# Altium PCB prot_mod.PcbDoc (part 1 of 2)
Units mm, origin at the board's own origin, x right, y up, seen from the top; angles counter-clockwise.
Board outline 113 x 90 mm, 2 copper layers (Top Layer, Bottom Layer), stack 1.562 mm thick; 112 components, 43 nets, 249 pads, 37 vias.
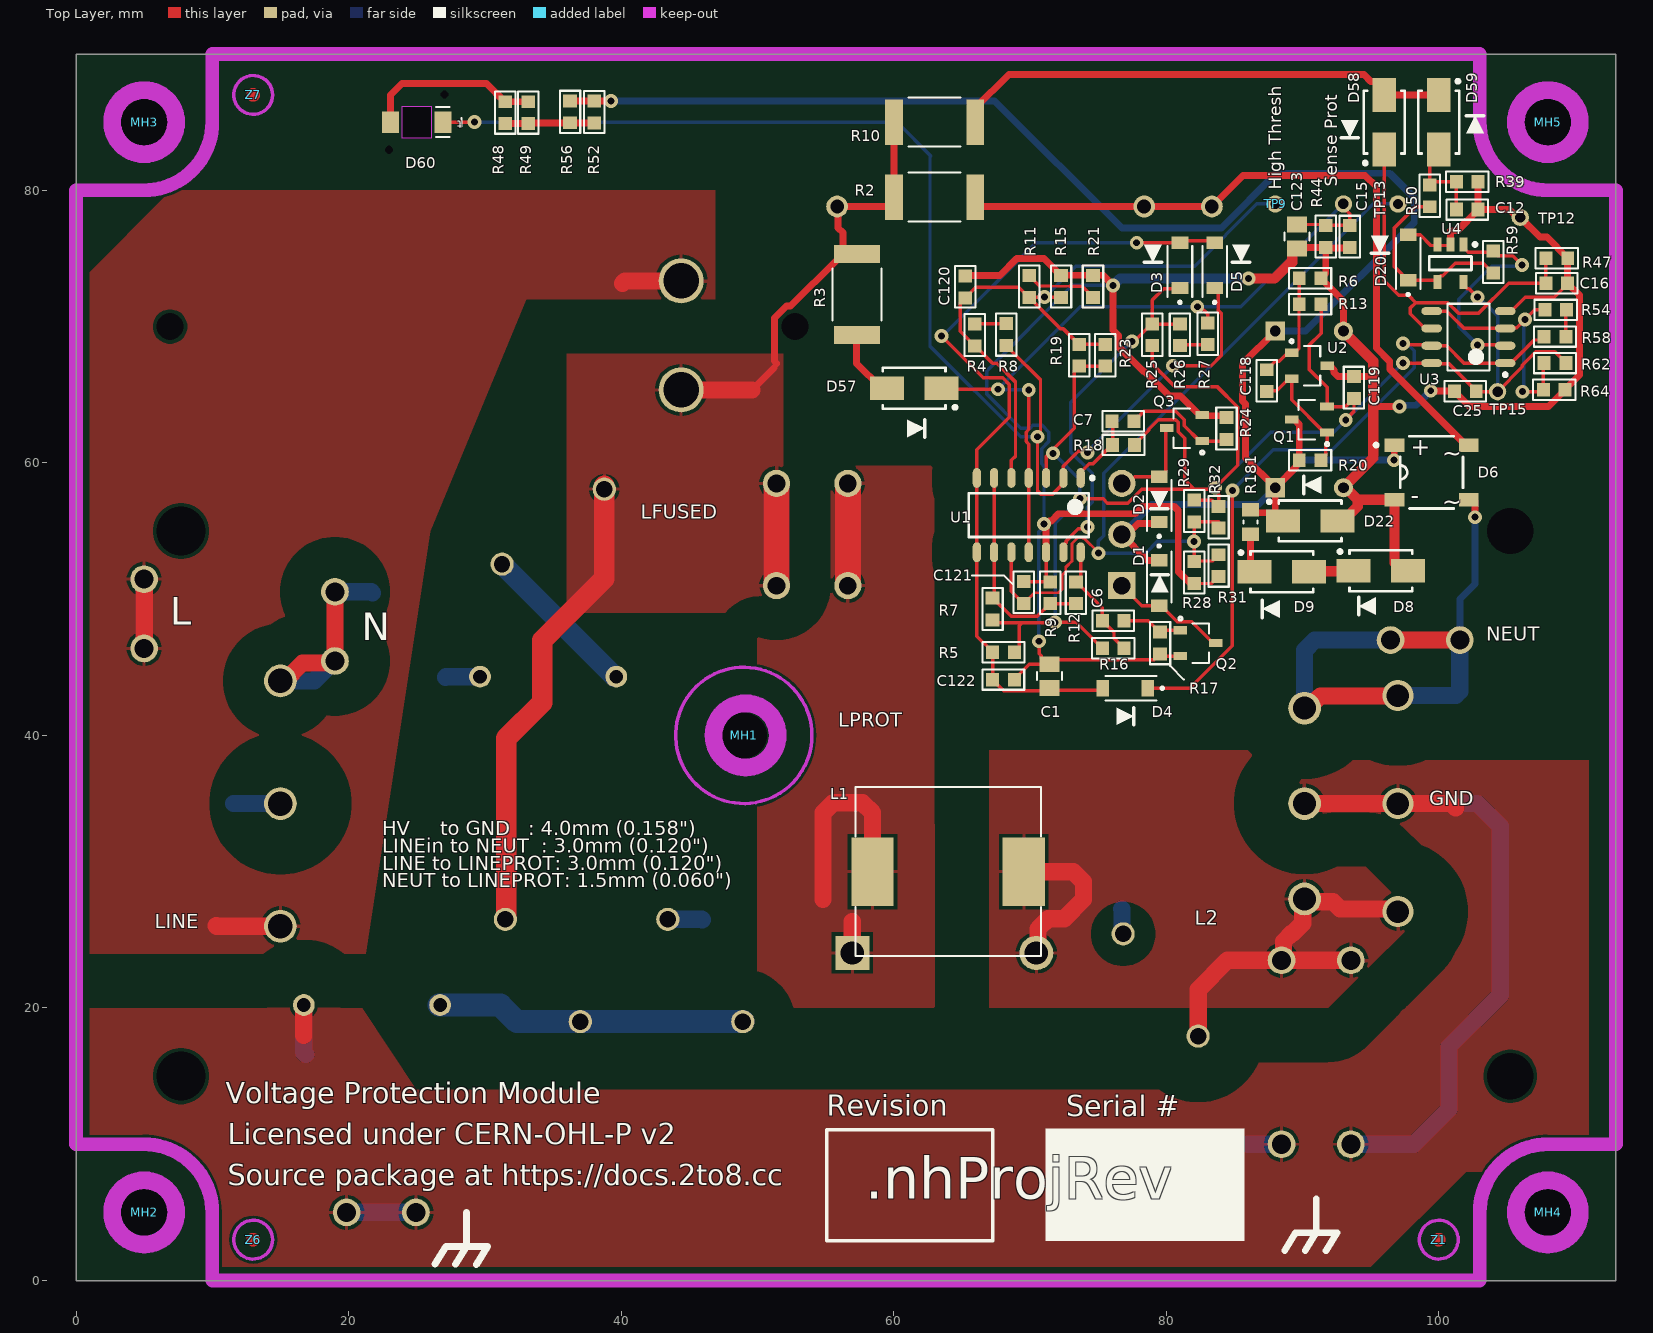
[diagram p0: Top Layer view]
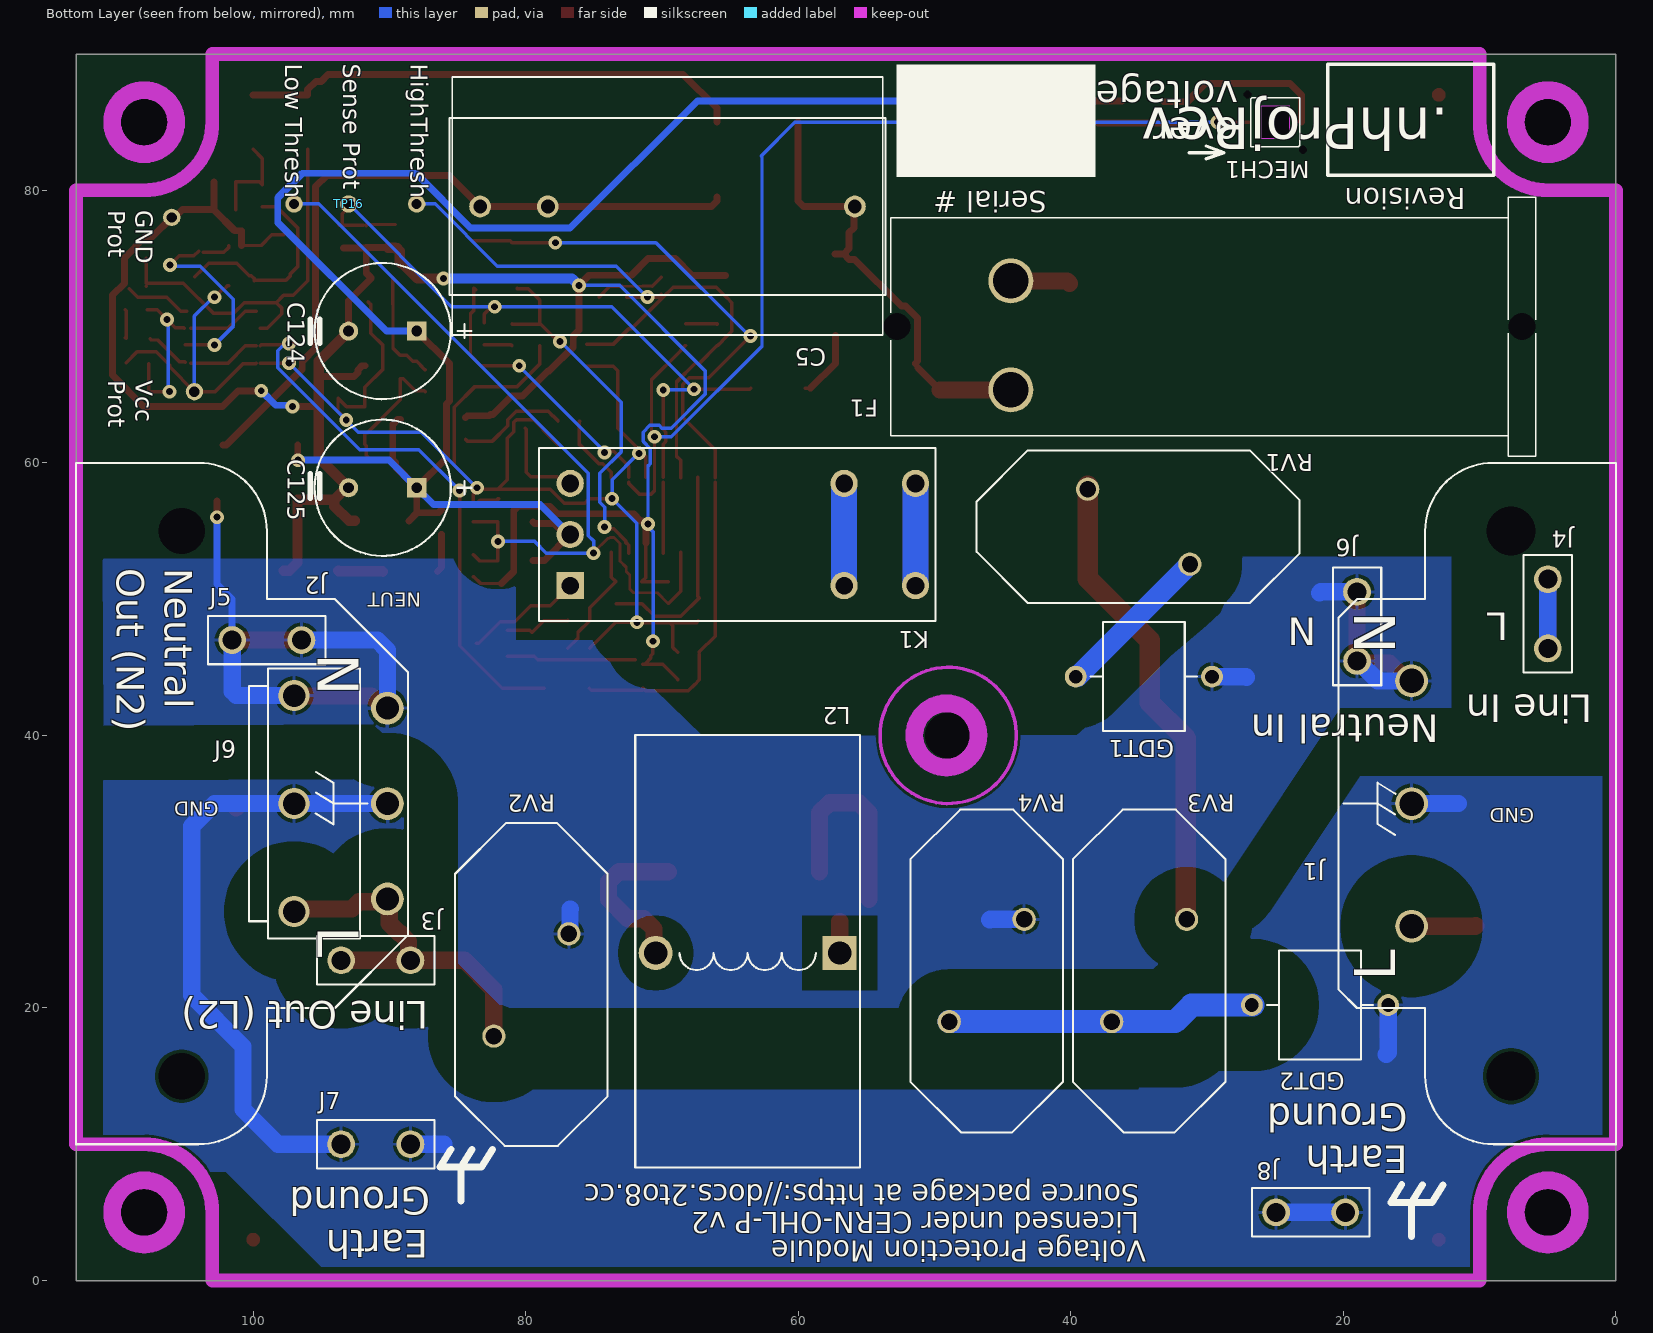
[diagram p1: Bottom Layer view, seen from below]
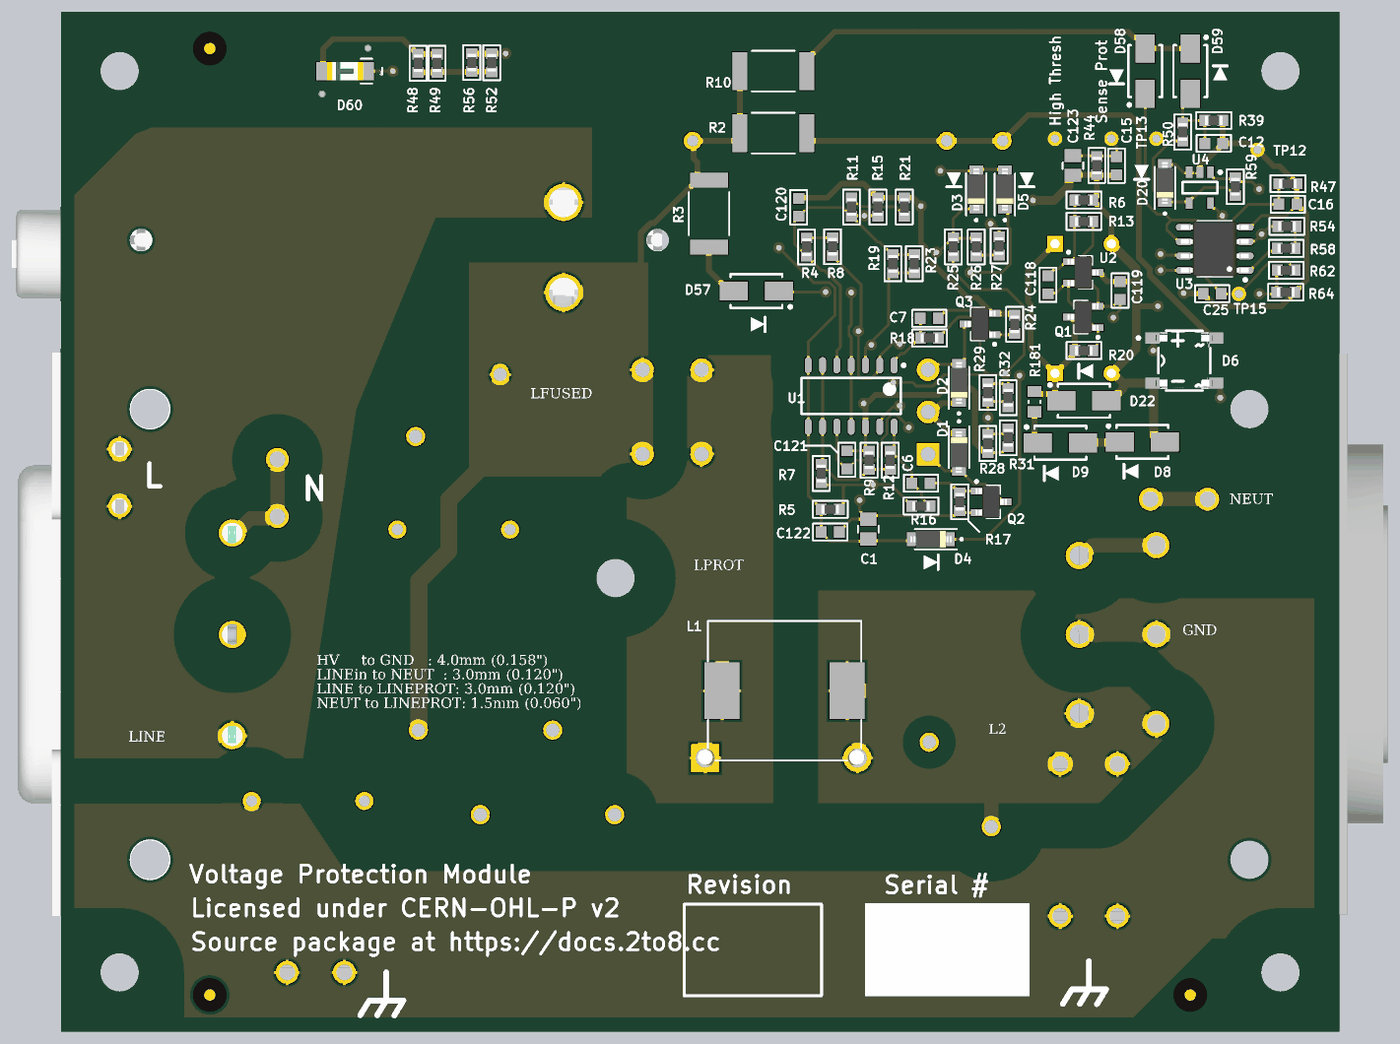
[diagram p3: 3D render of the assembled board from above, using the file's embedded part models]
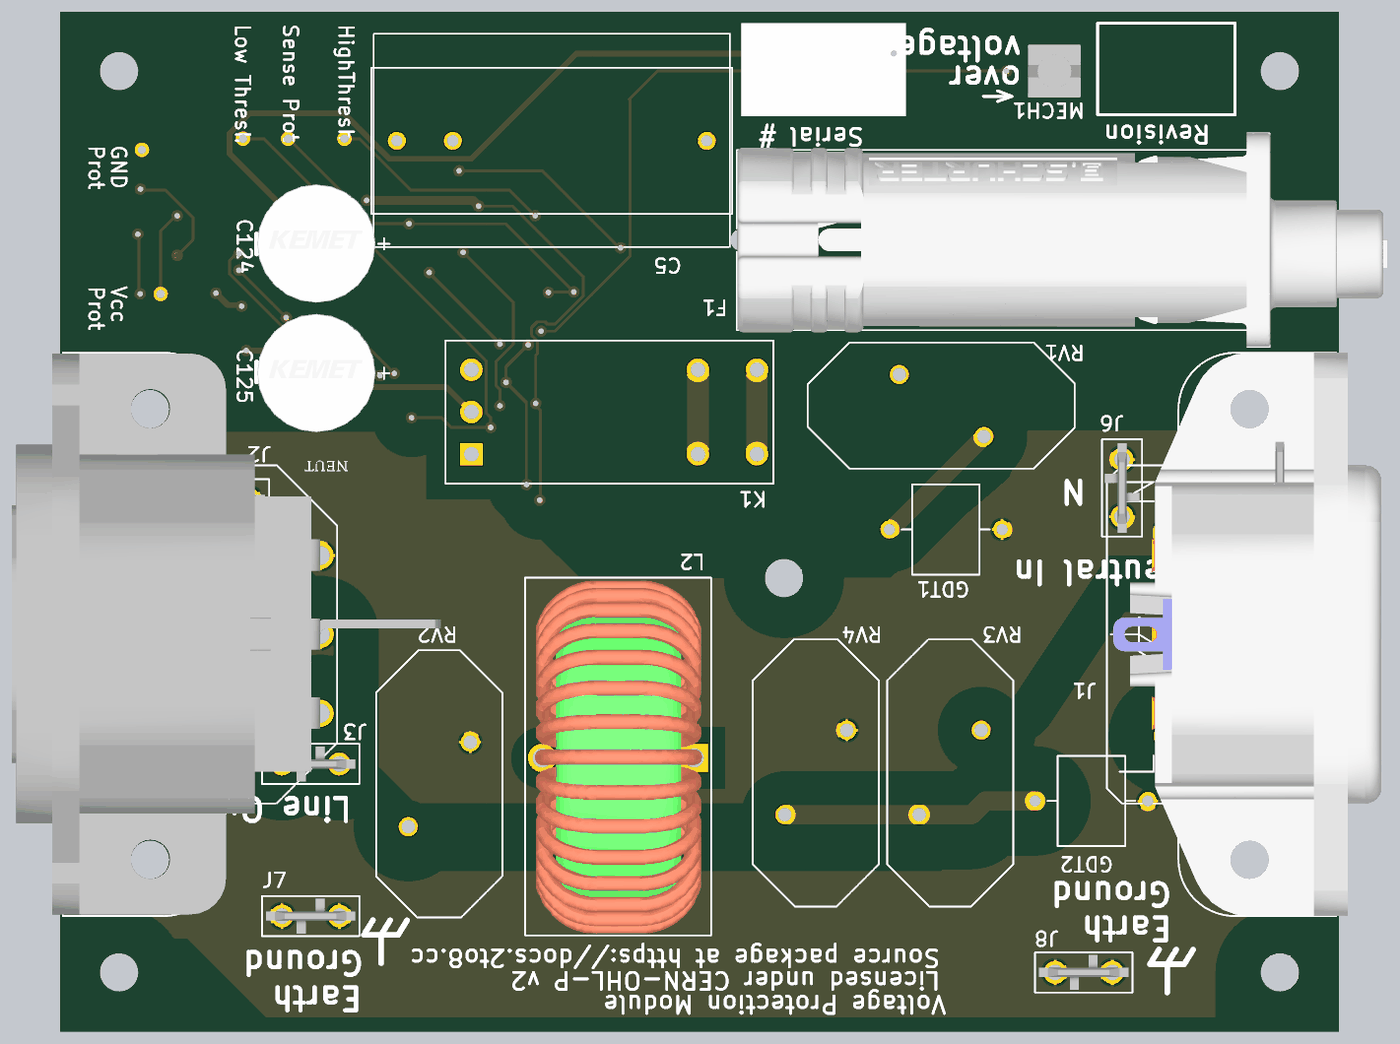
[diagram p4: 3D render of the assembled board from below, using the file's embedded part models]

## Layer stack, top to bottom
Top Solder: solder mask 0.0102, Solder Resist, Dk 3.5
Top Layer: signal copper 0.07
Dielectric 1: prepreg 1.4224, FR-4, Dk 4.5
Bottom Layer: signal copper 0.07
Bottom Solder: solder mask 0.0102, Solder Resist, Dk 3.5

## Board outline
0,0 113,0 113,90 0,90

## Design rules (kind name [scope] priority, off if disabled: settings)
AssemblyTestPointUsage [All] p1 off:
AssemblyTestpoint [All] p1 off: testpointundercomponent=TRUE minsize=1.016 maxsize=2.54 preferedsize=1.524 minholesize=0 maxholesize=1.016 preferedholesize=0.813 testpointgrid=0.025 usegrid=TRUE gridtolerance=0 allowsidetop=TRUE allowsidebottom=TRUE
Clearance Clearance_1_Line_SELV_FG [InNetClass('Line') vs InNetClass('SELV') or InNetClass('FG')] p1: gap=4 ignorepadtopadclearanceinfootprint=FALSE // REINFORCED for separated extremely low voltage
Clearance Clearance_2_LineProt_SELV_FG [InNetClass('LineProt') vs InNetClass('SELV') or InNetClass('FG')] p2: gap=4 ignorepadtopadclearanceinfootprint=FALSE // REINFORCED for separated extremely low voltage
Clearance Clearance_3_Neut_SELV_FG [InNetClass('Neut') vs InNetClass('SELV') or InNetClass('FG')] p3: gap=4 ignorepadtopadclearanceinfootprint=FALSE // REINFORCED for separated extremely low voltage
Clearance Clearance_4_Line_LineProt [InNetClass('Line') vs InNetClass('LineProt')] p4: gap=3 ignorepadtopadclearanceinfootprint=TRUE except(0: Arc-Hole Track-Hole SMDPad-Hole THPad-Hole Via-Hole Fill-Hole Poly-Hole Region-Hole Text-Hole) // FUNCTIONAL insulation for LN before relay (700Vrms/990VPeak)
Clearance Clearance_5_Neut_LineProt [InNetClass('Neut') vs InNetClass('LineProt')] p5: gap=1.5 ignorepadtopadclearanceinfootprint=TRUE except(0: Arc-Hole Track-Hole SMDPad-Hole THPad-Hole Via-Hole Fill-Hole Poly-Hole Region-Hole Text-Hole) // FUNCTIONAL insulation for 240VAC nominal
Clearance Clearance_6_Line_Neut [InNetClass('Line') vs InNetClass('Neut')] p6: gap=3 ignorepadtopadclearanceinfootprint=TRUE // more FUNCTIONAL insulation for 240VAC nominal
Clearance [All] p7: gap=0.2 ignorepadtopadclearanceinfootprint=TRUE except(0.25: Arc-Hole Track-Hole SMDPad-Hole THPad-Hole Via-Hole Fill-Hole Poly-Hole Region-Hole Text-Hole)
DiffPairsRouting [All] p1: maxlimit=0.254 minlimit=0.203 mostfreqgap=0.203 toplayer_minwidth=0.203 toplayer_maxwidth=0.368 toplayer_prefwidth=0.368 bottomlayer_minwidth=0.203 bottomlayer_maxwidth=0.368 bottomlayer_prefwidth=0.368 maxuncoupledlength=12.7
FabricationTestPointUsage [All] p1 off: valid=0 allowmultiple=FALSE
FabricationTestpoint [All] p1 off: side=3 testpointundercomponent=TRUE minsize=1.016 maxsize=2.54 preferedsize=1.524 minholesize=0 maxholesize=1.016 preferedholesize=0.813 testpointgrid=0.025 allowsidetop=TRUE allowsidebottom=TRUE usegrid=TRUE gridtolerance=0
Height [All] p1 off: minheight=0 maxheight=25.4 prefheight=12.7
HoleSize [All] p1: absolutevalues=TRUE maxlimit=5.08 minlimit=0.203 maxpercent=80.000 minpercent=20.000
MinimumAnnularRing [All] p1: minimumring=0.229
MinimumSolderMaskSliver [All] p1: minsoldermaskwidth=0.02
PolygonConnect [All] p1: connectstyle=Relief reliefconductorwidth=0.254 reliefentries=4 polygonreliefangle="90 Angle" airgapwidth=0.254
RoutingVias [All] p1: holewidth=0.508 width=1.016 viastyle="Through Hole" minholewidth=0.254 minwidth=0.711 maxholewidth=1.27 maxwidth=1.778
SMDNeckDown [All] p1: percent=90.000
SilkToSilkClearance [All] p1 off: silktosilkclearance=0.254
SilkToSolderMaskClearance [IsPad] p1: minsilkscreentomaskgap=0.127 clearancetoexposedcopper=TRUE
SolderMaskExpansion [All] p1: expansion=0.102 istentingtop=FALSE
SupplyNets "Schematic Supply Nets_3" [InNet('GND')] p1: voltage=0.000
SupplyNets "Schematic Supply Nets_2" [InNet('GND_PROT')] p2: voltage=0.000
SupplyNets "Schematic Supply Nets_1" [InNet('Vcc_prot')] p3: voltage=0.000
SupplyNets "Schematic Supply Nets" [InNet('Vcoil')] p4: voltage=0.000
Width [All] p1: maxlimit=7.62 minlimit=0.178 preferedwidth=0.254
20 further rules are at their usual default settings.

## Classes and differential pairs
net class FG: GND
component class Cover: MH1 MH2 MH3 MH4 MH5 Z1 Z6 Z7 Z15 Z16 Z17 Z18 Z19 Z20 Z21 Z22 Z23 Z24 Z25 Z26 Z27 Z28 Z29 Z30 Z31
net class Line: GND_PROT input_ok LFUSED LINE NC.MOV5 NetC5_2 NetC6_2 NetC7_2 NetC118_1 NetC118_2 NetD8_K NetD9_K NetD20_K NetD57_A NetD58_A NetD60_A NetGDT1_2 NetR4_1 NetR7_2 NetR11_1 NetR26_1 NetR48_1 NetR54_1 overvoltage# peak_neg peak_neg_inv peak_out peak_pos peak_thresh PROT_RESET PROT_SET ref_high ref_low reset sense_prot set undervoltage# VCC_PROT VCOIL
net class Neut: NEUT
net class LineProt: L2 LPROT
component class PowerHV: asdf F1 GDT1 GDT2 J1 J2 J3 J4 J5 J6 J7 J8 J9 K1 L1 L2 RV1 RV2 RV3 RV4
component class Protect: C1 C5 C6 C7 C12 C15 C16 C25 C118 C119 C120 C121 C122 C123 C124 C125 D1 D2 D3 D4 D5 D6 D8 D9 D20 D22 D57 D58 D59 D60 MECH1 Q1 Q2 Q3 R2 R3 R4 R5 R6 R7 R8 R9 R10 R11 R12 R13 R15 R16 R17 R18 R19 R20 R21 R23 R24 R25 R26 R27 R28 R29 R31 R32 R39 R44 R47 R48 R49 R50 R52 R54 R56 R58 R59 R62 R64 R181 TP9 TP12 TP13 TP15 TP16 U1 U2 U3 U4

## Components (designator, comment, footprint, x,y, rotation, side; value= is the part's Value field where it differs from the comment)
C1 "CL21A226MOCLRNC" CAPC2012X135,0805, 71.423,44.354 r90 top value=22uF
C5 "R586R333050T0K" CAP_RAD28P3213X22 69.6,78.809 r0 bottom locked value=0.33uF
C6 "CL10B333KB8NNNC" CAPC1608X09N[0603] 76.108,48.421 r0 top value=33n
C7 "CL10B333KB8NNNC" CAPC1608X09N[0603] 76.832,63.065 r0 top value=33n
C12 "CL10B104KB8NNNL" CAPC1608X09N[0603] 102.087,78.588 r0 top value=0.1u
C15 "CL10B104KB8NNNL" CAPC1608X09N[0603] 93.457,76.605 r270 top value=0.1u
C16 "CL10B104KB8NNNL" CAPC1608X09N[0603] 108.653,73.186 r0 top value=0.1u
C25 "CL10B104KB8NNNL" CAPC1608X09N[0603] 101.947,65.247 r180 top value=0.1u
C118 "CL10B333KB8NNNC" CAPC1608X09N[0603] 87.38,66.034 r90 top value=33n
C119 "CL10A475KA8NQNC" CAPC1608X09N[0603] 93.775,65.525 r90 top value=4.7u
C120 "CL10B104KB8NNNL" CAPC1608X09N[0603] 65.251,72.911 r90 top value=0.1u
C121 "CL10B104KB8NNNL" CAPC1608X09N[0603] 69.538,50.493 r90 top value=0.1u
C122 "CL10A475KA8NQNC" CAPC1608X09N[0603] 68.055,44.099 r0 top value=4.7u
C123 "CL21A226MOCLRNC" CAPC2012X135,0805, 89.591,76.616 r270 top value=22uF
C124 "ESH477M035AH3AA" CAP_RAD5P_CYL_10X20 90.5,69.669 r180 bottom value=470uF
C125 "ESH477M035AH3AA" CAP_RAD5P_CYL_10X20 90.5,58.175 r180 bottom value=470uF
D1 "1N4148W-TP" SOD-123 79.474,51.187 r270 top
D2 "1N4148W-TP" SOD-123 79.475,57.32 r90 top
D3 "1N4148W-TP" SOD-123 81.006,74.491 r90 top
D4 "1N4148W-TP" SOD-123 76.992,43.454 r180 top
D5 "1N4148W-TP" SOD-123 83.546,74.491 r90 top
D6 "ABS10" SOP400P640X170-4N_BRIDGE 99.476,59.304 r0 top
D8 "SMAZ8V2-13-F" DO-214AC 95.748,52.087 r0 top value=8.2V
D9 "SMAZ8V2-13-F" DO-214AC 88.476,52.013 r0 top value=8.2V
D20 "MBR130T1G" SOD-123 97.747,75.065 r90 top
D22 "SMAJ24A-13-F" DO-214AC 90.56,55.743 r0 top
D57 "S1V" DO-214AC 61.5,65.477 r180 top
D58 "S1V" DO-214AC 96,85 r90 top
D59 "S1V" DO-214AC 100,85 r270 top
D60 "APTR3216SURCK" LEDC3216X08NREDBOT,1206, 25,85 r180 top
F1 "SCHURTER_4404.0102" SCHURTER_T9-818 29.5,70 r0 bottom
GDT1 "CG31.0L" LITTELFUSE_CG3x 34.645,44.312 r0 bottom
GDT2 "CG32.5L" LITTELFUSE_CG3x 21.716,20.216 r180 bottom
J1 "703W-00/54" QUALTEK_703W-00/54 11.35,35 r90 bottom
J2 "PX0675/PC" BULGIN_PX0675/PC 105.25,35 r270 bottom
J3 "TE_63849-1" AMP_63849-1 91,23.5 r180 bottom
J4 "TE_63849-1" AMP_63849-1 5,48.921 r270 bottom
J5 "TE_63849-1" AMP_63849-1 99,47 r180 bottom
J6 "TE_63849-1" AMP_63849-1 19,48 r270 bottom
J7 "TE_63849-1" AMP_63849-1 91,10 r180 bottom
J8 "TE_63849-1" AMP_63849-1 22.402,5 r180 bottom
J9 "AMP/TE_1-1123724-3" AMP_1-1123724-3 97,35 r90 bottom
K1 "TE_CONN_2-1415898-5" TE_RT1_2COIL_LATCHING 64.488,54.743 r90 bottom
L1 "SRP1265CC-220M" INDUCTOR-BOURNS_SRP1265CC 64,30 r0 top value=22uH
L2 "BELFUSE_HCTI-47-10.7" BELFUSE_HCTI_TOROIDAL_INDUCTOR 63.714,24.036 r270 bottom value=47uH
MECH1 "VLP-400-F" BIVAR_VLP-400-F 25,85 r270 bottom
MH1 "MOUNTING_HOLE_3MM_UNPLATED" MOUNT_HOLE_3MM_NOCOPPER#1 49.132,40 r90 top
MH2 "MOUNTING_HOLE_3MM_UNPLATED" MOUNT_HOLE_3MM_NOCOPPER#2 5,5 r90 top
MH3 "MOUNTING_HOLE_3MM_UNPLATED" MOUNT_HOLE_3MM_NOCOPPER#2 5,85 r90 top
MH4 "MOUNTING_HOLE_3MM_UNPLATED" MOUNT_HOLE_3MM_NOCOPPER#2 108,5 r90 top
MH5 "MOUNTING_HOLE_3MM_UNPLATED" MOUNT_HOLE_3MM_NOCOPPER#2 108,85 r90 top
Q1 "BCV72,215" SOT95P275X125-3N 90.5,63.175 r180 top
Q2 "IRLML6346TRPBF" SOT95P275X125-3N 82.337,46.772 r0 top
Q3 "IRLML6346TRPBF" SOT95P275X125-3N 81.339,62.551 r180 top
R2 "CHV2512-FX-1004ELF" RESC6534X70,2512, 63,79.5 r0 top value=1M
R3 "CHV2512-FX-1004ELF" RESC6534X70,2512, 57.303,72.35 r270 top value=1M
R4 "ERJ-3EKF4753V" RESC1608X05AN[0603] 65.956,69.379 r270 top value=475k
R5 "ERJ-3EKF1004V" RESC1608X05AN[0603] 68.055,46.105 r180 top value=1M
R6 "ERA-3AEB4221V" RESC1608X05AN[0603] 90.56,73.559 r0 top value=4.22k
R7 "ERJ-3EKF1003V" RESC1608X05AN[0603] 67.255,49.281 r90 top value=100k
R8 "ERJ-3EKF1004V" RESC1608X05AN[0603] 68.258,69.411 r270 top value=1M
R9 "ERJ-3EKF1003V" RESC1608X05AN[0603] 71.496,50.465 r90 top value=100k
R10 "CHV2512-FX-1004ELF" RESC6534X70,2512, 63,85 r0 top value=1M
R11 "ERA-3AEB1742V" RESC1608X05AN[0603] 69.938,72.936 r270 top value=17.4k
R12 "ERJ-3EKF1004V" RESC1608X05AN[0603] 73.376,50.465 r90 top value=1M
R13 "ERA-3AEB2742V" RESC1608X05AN[0603] 90.56,71.652 r180 top value=27.4k
R15 "RMCF0603FT140K" RESC1608X05AN[0603] 72.281,72.936 r90 top value=140k
R16 "RMCF0603FT10K0" RESC1608X05AN[0603] 76.108,46.389 r0 top value=10k
R17 "ERJ-3EKF4753V" RESC1608X05AN[0603] 79.543,46.772 r90 top value=475k
R18 "RMCF0603FT10K0" RESC1608X05AN[0603] 76.857,61.313 r180 top value=10k
R19 "ERA-3AEB2742V" RESC1608X05AN[0603] 73.609,67.898 r90 top value=27.4k
R20 "RMCF0603FT2K74" RESC1608X05AN[0603] 90.56,60.196 r180 top value=2.74k
R21 "ERJ-3EKF2210V" RESC1608X05AN[0603] 74.624,72.936 r90 top value=221
R23 "ERJ-3EKF1004V" RESC1608X05AN[0603] 75.514,67.898 r90 top value=1M
R24 "ERJ-3EKF4753V" RESC1608X05AN[0603] 84.421,62.525 r270 top value=475k
R25 "ERA-3AEB2742V" RESC1608X05AN[0603] 78.975,69.397 r270 top value=27.4k
R26 "ERJ-3EKF1004V" RESC1608X05AN[0603] 81.007,69.397 r90 top value=1M
R27 "ERJ-3EKF1004V" RESC1608X05AN[0603] 83.039,69.473 r270 top value=1M
R28 "ERJ-3EKF3322V" RESC1608X05AN[0603] 82.046,51.949 r270 top value=33.2k
R29 "RMCF0603FT140K" RESC1608X05AN[0603] 82.046,56.47 r270 top value=140k
R31 "ERA-3AEB3401V" RESC1608X05AN[0603] 83.836,52.457 r270 top value=3.4k
R32 "ERA-3AEB2742V" RESC1608X05AN[0603] 83.836,56.013 r270 top value=27.4k
R39 "ERA-3AEB4221V" RESC1608X05AN[0603] 102.087,80.62 r0 top value=4.22k
R44 "ERA-3AEB2742V" RESC1608X05AN[0603] 91.705,76.616 r270 top value=27.4k
R47 "ERA-3AEB4221V" RESC1608X05AN[0603] 108.659,75.008 r0 top value=4.22k
R48 "ERJ-3EKF1001V" RESC1608X05AN[0603] 31.486,85.697 r90 top value=1k
R49 "ERJ-3EKF1001V" RESC1608X05AN[0603] 33.171,85.697 r90 top value=1k
R50 "ERJ-3EKF1003V" RESC1608X05AN[0603] 99.331,79.595 r270 top value=100k
R52 "ERJ-3EKF1001V" RESC1608X05AN[0603] 38.014,85.743 r270 top value=1k
R54 "ERJ-3EKF4753V" RESC1608X05AN[0603] 108.581,71.221 r180 top value=475k
R56 "ERJ-3EKF1001V" RESC1608X05AN[0603] 36.25,85.758 r270 top value=1k
R58 "ERJ-3EKF1004V" RESC1608X05AN[0603] 108.525,69.267 r180 top value=1M
R59 "ERJ-3EKF1003V" RESC1608X05AN[0603] 104,74.735 r90 top value=100k
R62 "ERA-3AEB2742V" RESC1608X05AN[0603] 108.525,67.323 r180 top value=27.4k
R64 "ERA-3AEB622V" RESC1608X05AN[0603] 108.474,65.374 r0 top value=6.2k
R181 "ERJ-P06F1000V" RESC2012X06N,0805, 86.179,55.66 r270 top value=100
RV1 "TMOV20RP300E" MOV_RAD7.5P5.5S_DISC_20X11.5 35.013,55.317 r0 bottom
RV2 "TMOV20RP300E" MOV_RAD7.5P5.5S_DISC_20X11.5 79.588,21.684 r90 bottom
RV3 "TMOV20RP300E" MOV_RAD7.5P5.5S_DISC_20X11.5 34.254,22.75 r270 bottom
RV4 "TMOV20RP300E" MOV_RAD7.5P5.5S_DISC_20X11.5 46.176,22.75 r270 bottom
TP9 "TP TH  0.78mm" TP_TH078H127P#1 88,79 r0 top
TP12 "TP TH  0.78mm" TP_TH078H127P#2 106,78 r0 top
TP13 "TP TH  0.78mm" TP_TH078H127P#1 97,79 r0 top
TP15 "TP TH  0.78mm" TP_TH078H127P#3 104.314,65.222 r90 top
TP16 "TP TH  0.78mm" TP_TH078H127P#3 93,79 r0 bottom
U1 "LP2901DR" SOIC127P600X175-14N 69.91,56.165 r270 top
U2 "TS3431CILT" SOT95P275X125-3N 90.5,67.125 r0 top
U3 "TS393IDT" SOIC127P600X175-8N 102.176,69.228 r180 top
U4 "TLV2401IDBVR" SOT95P280X145-5N 100.856,74.651 r270 top
Z1 "FIDUCIAL_1_3" FIDUCIAL_1_3_KEEPOUT 100,3 r90 top
Z6 "FIDUCIAL_1_3" FIDUCIAL_1_3_KEEPOUT 13,3 r0 top
Z7 "FIDUCIAL_1_3" FIDUCIAL_1_3_KEEPOUT 13,87 r0 top

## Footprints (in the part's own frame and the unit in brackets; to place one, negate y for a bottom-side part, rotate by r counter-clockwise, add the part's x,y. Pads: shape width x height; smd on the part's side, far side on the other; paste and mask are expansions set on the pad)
AMP_1-1123724-3 [mm] "0.156\" (3.96mm) pitch header with latch, alternating pins"
  round 2.3 hole 1.65: 1(-7.925,0) 3(0,0) 5(7.925,0)
  silkscreen extent -9.91,-4.83 9.91,3.3, body extent -9.87,-4.8 9.87,3.7, height 10.75
AMP_63849-1 [mil] "PCB-mount 0.250\" (or 0.187\") wide quick connect terminal, male vertical"
  round 80 hole 55: 1(-100,0) 1(100,0)
  silkscreen extent -170,-70 170,70, body extent -156,-61 156,61, height 409
BELFUSE_HCTI_TOROIDAL_INDUCTOR [mm] "BelFuse HCTI series high-current toroidal inductor.  13.5 mm pitch, 33 mm diameter vertical toroid"
  rect 2.5x2.5 hole 1.7: 1(0,6.75)
  round 2.5 hole 1.7: 2(0,-6.75)
  silkscreen extent -16,-8.25 15.75,8.25, body extent -15.75,-7.37 15.61,7.44, height 31.41
BIVAR_VLP-400-F [mm] "Light Pipe Single Clear Rigid Board Mount, Press Fit"
  round 0.3 hole 0.61 unplated: 1(2.032,2.032) 2(-2.032,-2.032)
  silkscreen extent -1.8,-1.8 1.8,1.8, body extent -2.35,-2.35 2.35,2.35, height 10.16
BULGIN_PX0675/PC [mm] "Mains power inlet IEC 320-F (like a C13, but panel mount) with 7 mm pin pitch."
  round 2.4 hole 1.7: 1(7,15.1) 2(-7,15.1) 3(0,15.1)
  round 2 hole 3.4 unplated: ML(-20,0) MN(20,0)
  silkscreen extent -25,-7.75 25,16.6, body extent -24.94,-12.25 24.86,25.79, height 30.2
CAP_RAD5P_CYL_10X20 [mm] "Radial electrolytic 5 mm pitch 10 mm dia, 20 mm high with + and - terminals."
  rect 1.4x1.4 hole 0.8: +(2.5,0)
  round 1.4 hole 0.8: -(-2.5,0)
  silkscreen extent -5,-5 6.5,5, body extent -5.25,-5.22 5.25,5.28, height 22
CAP_RAD28P3213X22 [mm] "Box capacitor 27.5 mm pin pitch, 31.5 mm length, 13 mm width, 22 mm height"
  round 1.6 hole 1: 1(-13.75,0) 2(13.75,0)
  silkscreen extent -16,-6.5 16,6.5, body extent -16,-6.5 16,6.5, height 22
CAPC1608X09N[0603] [mm] "Chip Capacitor, Body 1.6x0.8mm, IPC Medium Density, 0603 imperial with silk box"
  rect 0.95x1 smd: 1(-0.8,0) 2(0.8,0)
  silkscreen extent -1.53,-0.75 1.53,0.75, body extent -0.85,-0.45 0.85,0.45, height 0.9
CAPC2012X135,0805, [mm] "Chip Capacitor, Body 2.0x1.2mm, IPC Medium Density, Height 1.35 mm, 0805 imperial with minimal silk"
  rect 1.16x1.47 smd: 1(-0.875,0) 2(0.875,0)
  silkscreen extent -0.3,-0.92 0.3,0.92, body extent -1,-0.63 1,0.63, height 1.35
DO-214AC [mm] "SMA Molded Diode, 2-Leads, Body 4.30x2.61mm, IPC Medium Density with A and K pads"
  rect 2.5x1.7 smd: A(2,0) K(-2,0)
  silkscreen extent -3.12,-1.5 2.3,1.52, body extent -2.3,-1.46 2.3,1.46, height 2.4
FIDUCIAL_1_3_KEEPOUT [mm] "1mm dia fiducial with 3mm dia keepout"
  Top Layer circle w0.5: c0,0 r0.25
  Top Layer keep-out circle w0.254: c0,0 r1.425
INDUCTOR-BOURNS_SRP1265CC [mm] "SMT inductor 12 mm square, 6.5 mm high, with 4.7 mm wide terminals"
  rect 3.1x5 smd: 1(-5.55,0) 2(5.55,0)
  silkscreen extent -6.81,-6.2 6.81,6.2, body extent -6,-6 6,6, height 6.5
LEDC3216X08NREDBOT,1206, [mm] "Chip LED Body 3.2x1.6mm, IPC Medium Density, red, board cutout for bottom projection"
  rect 1.237x1.6 smd: A(1.932,0) K(-1.932,0)
  Keep-Out Layer board cut-out: -1.075,1.175 1.075,1.175 1.075,-1.175 -1.075,-1.175
  silkscreen extent -3.3,-1.1 -1.4,1.1, body extent -1.6,-0.8 1.6,0.8, height 0.26
LITTELFUSE_CG3x [mm] "for gas discharge tubes and other wide axial components"
  round 1.6 hole 1: 1(-5,0) 2(5,0)
  silkscreen extent -3.9,-4 3.9,4, body extent -5.4,-4 5.4,4, height 8
MOUNT_HOLE_3MM_NOCOPPER#1 [mm] "Mounting hole for M3 screw, unplated"
  round 1 hole 3.4 unplated: 1(0,0.132)
  Keep-Out Layer circle w1.3: c0,0 r2.35
MOUNT_HOLE_3MM_NOCOPPER#2 [mm] "Mounting hole for M3 screw, unplated"
  round 1 hole 3.4 unplated: 1(0,0)
  Keep-Out Layer circle w1.3: c0,0 r2.35
MOV_RAD7.5P5.5S_DISC_20X11.5 [mm] "MOV radial disc, 7.5 mm pitch with 5.5 mm offset, 20 mm dia. 11.5 mm thick, max height 26 mm."
  round 1.7 hole 1.2: 1(-3.75,2.75) 2(3.75,-2.75)
  silkscreen extent -11.8,-5.6 11.9,5.6, body extent -12,-5.75 12,5.75, height 28
QUALTEK_703W-00/54 [mm] "Mains power inlet IEC 320-C14 with 9 mm pin pitch."
  round 2.4 hole 1.8: 1(-9,3.65) 2(9,3.65) 3(0,3.65)
  round 2 hole 3.6 unplated: ML(-20,-3.65) MN(20,-3.65)
  silkscreen extent -25,-11.35 25,9, body extent -25,-15.37 25,8.43, height 28.1
RESC1608X05AN[0603] [mm] "Chip Resistor, Body 1.6x0.8mm, IPC Medium Density, 0603 imperial with silk box"
  rect 0.95x1 smd: 1(-0.8,0) 2(0.8,0)
  silkscreen extent -1.55,-0.75 1.55,0.75, body extent -0.8,-0.4 0.8,0.4, height 0.55
RESC2012X06N,0805, [mm] "Chip Resistor, 2-Leads, Body 2.00x1.20mm, IPC Medium Density, 0805 imperial, minimal silk"
  rect 1x1.25 smd: 1(-0.9,0) 2(0.9,0)
  silkscreen extent -0.1,-0.53 0.1,0.53, body extent -1.05,-0.63 1.05,0.63, height 0.6
RESC6534X70,2512, [mm] "Chip Resistor, 2-Leads, Body 6.5x3.4mm, IPC Medium Density, Height 0.75 mm, 2512 imperial, minimal silk"
  rect 1.3x3.35 smd: 1(-2.975,0) 2(2.975,0)
  silkscreen extent -1.9,-1.8 1.9,1.8, body extent -3.25,-1.65 3.25,1.65, height 0.7
SCHURTER_T9-818 [mm] "Circuit Breaker, PCB mount horizontal, Schurter T9-818 series."
  round 3.3 hole 2.6: 1(14.9,4.65) 2(14.9,-3.35)
  round 1.5 hole 2 unplated: M1(-22.6,0) M2(23.25,0)
  silkscreen extent -23.6,-9.5 23.7,9.5, body extent -34.05,-9.52 23.65,9.48, height 14.6
SOD-123 [mil] "SOD-123 SMD diode with A and K pads"
  rect 36x48 smd: A(65.35,0) K(-65.35,0)
  silkscreen extent -111,-35 56,35, body extent -73,-31 73,32, height 53
SOIC127P600X175-8N [mm] "SOIC, 8-Leads, Body 4.90x3.90mm, Pitch 1.27mm, IPC Medium Density, SO-8"
  oval 1.5x0.6 smd: 1(-2.7,1.905) 2(-2.7,0.635) 3(-2.7,-0.635) 4(-2.7,-1.905) 5(2.7,-1.905) 6(2.7,-0.635) 7(2.7,0.635) 8(2.7,1.905)
  silkscreen extent -2.83,-2.45 1.55,2.88, body extent -3,-2.45 3,2.45, height 1.75
SOIC127P600X175-14N [mm] "SOIC, 14-Leads, Body 8.65x3.90mm, Pitch 1.27mm, IPC Medium Density, SO-14"
  oval 1.45x0.6 smd: 1(-2.725,3.81) 2(-2.725,2.54) 3(-2.725,1.27) 4(-2.725,0) 5(-2.725,-1.27) 6(-2.725,-2.54) 7(-2.725,-3.81) 8(2.725,-3.81) 9(2.725,-2.54) 10(2.725,-1.27) 11(2.725,0) 12(2.725,1.27) 13(2.725,2.54) 14(2.725,3.81)
  silkscreen extent -2.85,-4.4 1.6,4.79, body extent -2,-4.4 2,4.4, height 1.75
SOP400P640X170-4N_BRIDGE [mm] "Bridge Rectifier SOPA-4, SOP, 4-Leads, Body 5.05x4.40mm, Pitch 4.00mm, IPC Medium Density"
  rect 1.45x1 smd paste+0 mask+0: +(-2.725,2) -(-2.725,-2) AC1(2.725,2) AC2(2.725,-2)
  silkscreen extent -4.2,-2.65 2.3,2.65, body extent -3.55,-2.75 3.55,2.75, height 0.25
SOT95P275X125-3N [mm] "SOT23, 3-Leads, Body 2.90x2.75mm, Pitch 0.95mm, IPC Medium Density"
  rect 1x0.6 smd: 1(-1.3,0.95) 2(-1.3,-0.95) 3(1.3,0)
  silkscreen extent -1.43,-1.45 0.8,1.92, body extent -1.38,-1.45 1.38,1.45, height 1.25
SOT95P280X145-5N [mm] "SOT23, 5-Leads, Body 2.90x2.80mm, Pitch 0.95mm, IPC Medium Density"
  rect 1x0.6 smd: 1(-1.375,0.95) 2(-1.375,0) 3(-1.375,-0.95) 4(1.375,-0.95) 5(1.375,0.95)
  silkscreen extent -1.5,-1.55 0.5,1.92, body extent -0.88,-1.52 0.87,1.53, height 1.45
TE_RT1_2COIL_LATCHING [mm] "TE Connectivity/Schrack RT1/RT3 type latching SPST relay"
  round 2 hole 1.3: COM(-3.75,-7.85) COM(3.75,-7.85) NO(-3.75,-13.09) NO(3.75,-13.09) PLUS(0,12.25) SET(3.75,12.25)
  rect 2x2 hole 1.3: RESET(-3.75,12.25)
  silkscreen extent -6.35,-14.55 6.35,14.55, body extent -6.35,-14.55 6.35,14.55, height 16
TP_TH078H127P#1 [mil] "30mil Trough Hole Test Point"
  round 50 hole 29 mask+0: 1(0,0)
TP_TH078H127P#2 [mil] "30mil Trough Hole Test Point"
  round 50 hole 29 mask+0: 1(-0.98,0.54)
TP_TH078H127P#3 [mil] "30mil Trough Hole Test Point"
  round 50 hole 30 mask+0: 1(0,0)

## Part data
C1 C123: library part CMP-CAP-00014-1, "Multilayer Ceramic Capacitor, 22 uF, 16 V, ± 20%, X5R, 0805 [2012 Metric]", Case Code (Imperial)=0805, Case Code (Metric)=2012, Dielectric=X5R, Max Operating Temperature=85°C, Min Operating Temperature=-55°C, Package Quantity=1, Tolerance=20%, Voltage=16V
C5: library part CMP-CAP-00013-2, "CAP FILM 600VAC(X1) 0.33 UF 10%", Tolerance=10%, Voltage="600 VAC"
C6 C7 C118: library part CMP-CAP-00006-2, "Multilayer Ceramic Capacitor, 0.033 uF, 50 V, ± 10%, X7R, 0603 [1608 Metric]", Case Code (Imperial)=0603, Case Code (Metric)=1608, Dielectric=X7R, Max Operating Temperature=125°C, Min Operating Temperature=-55°C, Package Quantity=1, Tolerance=10%, Voltage=50V
C12 C15 C16 C25 C120 C121: library part CMP-CAP-00002-4, "Multilayer Ceramic Capacitor, 0.1 uF, 50 V, ± 10%, X7R, 0603 [1608 Metric]", Case Code (Imperial)=0603, Case Code (Metric)=1608, Dielectric=X7R, Max Operating Temperature=125°C, Min Operating Temperature=-55°C, Package Quantity=15000, Tolerance=10%, Voltage=50V
C119 C122: library part CMP-CAP-00007-2, "Multilayer Ceramic Capacitor, 4.7 uF, 25 V, ± 10%, X5R, 0603 [1608 Metric]", Case Code (Imperial)=0603, Case Code (Metric)=1608, Dielectric=X7R, Max Operating Temperature=85°C, Min Operating Temperature=-55°C, Package Quantity=1, Tolerance=10%, Voltage=25V
C124 C125: library part CMP-CAP-00011-2, "Capacitor; Al Electrolytic; Cap 470 uF; Tol 20%; Vol-Rtg 35 VDC; Radial; 10x17 mm", Case/Package=Radial, Max Operating Temperature=105°C, Min Operating Temperature=-40°C, Tolerance=20%, Voltage Rating (DC)=35V
D1 D2 D3 D4 D5: library part CMP-DIO-00000-3, "Rectifier Diode Switching 100V 0.3A 4ns 2-Pin SOD-123 T/R / DIODE GEN PURP 100V 150MA SOD123", Case/Package=SOD-123-2, Forward Current=150mA, Forward Voltage=1V, Power Dissipation=400mW, Voltage Rating (DC)=100V
D6: library part CMP-DIO-00006-2, "Bridge Rectifier Abs/Sopa-4 T&r 5K Rohs Compliant: Yes", Case/Package=SMD/SMT
D8 D9: library part CMP-DIO-00003-3, "DIODE ZENER 8.2V 1W SMA", Case/Package=SMA, Forward Current=1A, Forward Voltage=1.2V, Power Dissipation=1W, Voltage Rating (DC)=8.2V
D20: library part CMP-DIO-00001-3, "DIODE SCHOTTKY 30V 1A SOD123 / Rectifier Diode Schottky 30V 1A 2-Pin SOD-123 T/R", Case/Package=SOD-123-2, Forward Current=1A, Forward Voltage=470mV, Power Dissipation=400mW, Voltage Rating (DC)=30V
D22: library part CMP-DIO-00004-3, "SMAJ24A Series 400 W 24 V Surface Mount Uni-Directional TVS Diode - DO-214AC", Case/Package=SMA, Forward Current=1A, Forward Voltage=1.2V, Power Dissipation=400W, Voltage Rating (DC)=24V
D57 D58 D59: library part CMP-DIO-00007-2, "Diode Rectifier 2000V 1A 2-Pin DO-214AC T/R", Case/Package=SMA, Forward Current=1A, Forward Voltage=1V, Power Dissipation=1.4W, Voltage Rating (DC)=2kV
D60: library part CMP-LED-00004-1, "Red 3.2 x 1.6 x 1.05 mm (1206) 120º Water Clear 150 mcd 1.95 V Chip LED Lamp SMT", Case/Package=1206, Color=Red, Forward Current=20mA, Forward Voltage=1.95V, Max Operating Temperature=85°C, Min Operating Temperature=-40°C
F1: library part CMP-FUSE-00000-2, "Circuit Breaker Thermal 1P 240VAC/48DC 10A PCB Mnt-Thru-Hole Push Reset QC Term.", Voltage Rating (AC)=240V, Voltage Rating (DC)=48V
GDT1: library part CMP-PROT-00004-1, "CG3 Series - Two Terminal High Voltage Gas Plasma Arresters, 1000V, 10kA, plug in, RoHS", Breakdown Voltage=1.0kV
GDT2: library part CMP-PROT-00003-2, "Arrestor; 2500 V (min.) (breakdown); Rugged Ceramic-metal Package; 1 Pf (max.)", Breakdown Voltage=2.5kV
J1: library part CMP-CONN-00000-2, "Conn Electrical Power Inlet Right Angled Pin Cont 3 Cond 3 Poles Solder 250V"
J2: library part CMP-CONN-00001-2, "Conn Electrical Power Outlet Right Angled Pin Cont 3 Cond 3 Poles Solder 250V"
J3 J4 J5 J6 J7 J8: library part CMP-CONN-00004-1, "Quick Disconnect Terminal 12-24AWG Brass Tab 14.02mm Tin Over Copper/Tin Over Nickel Bag"
J9: library part CMP-CONN-00006-1, "Conn Power HDR 5 POS 3.96mm Solder ST Thru-Hole 5 Terminal 1 Port", Voltage Rating=250V
K1: library part CMP-RELAY-00000-2, "Electromechanical Relay SPST-NO 16A 12VDC 240Ohm Through Hole", Coil Power=600mW, Contact Current Rating=16A, Contact Voltage Rating (AC)=250V
L1: library part CMP-IND-00003-1, "Inductor Power Shielded Wirewound 22uH 20% 100KHz 20Q-Factor Carbonyl Powder 10A 0.037Ohm DCR"
L2: library part CMP-IND-00005-2, "47 µH Shielded Toroidal Inductor 10.7 A 16mOhm Max Radial, Vertical (Open)", Case/Package=Radial, Current Rating=10.7A, DC Resistance (DCR)=16mR, Max Operating Temperature=105°C, Min Operating Temperature=-55°C, Tolerance=15%
MECH1: library part CMP-LED-00003-5, "Light Pipe, Rigid, Vertical, Board Mount, SMD LED, .400 in., Flat Face"
MH1 MH2 MH3 MH4 MH5: library part CMP-NOBOM-00004-1, "Hole for M3 screw, unplated"
Q1: library part CMP-BJT-00000-1, "BCV72 Series 60 V 100 mA 250 mW NPN SMT General Purpose Transistor - SOT-23", Case/Package=TO-236-3, Collector Base Voltage (VCBO)=80V, Collector Emitter Voltage (VCEO)=60V, Frequency=100MHz, Max Collector Current=100mA
Q2 Q3: library part CMP-FET-00000-1, "MOSFET Transistor, N Channel, 3.4 A, 30 V, 0.046 ohm, 4.5 V, 800 mV", Case/Package=SOT-23, Continuous Drain Current (ID)=3.4A, Drain to Source Resistance=46mR, Drain to Source Voltage (Vdss)=30V
R2 R3 R10: library part CMP-RES-00067-2, "SMD Chip Resistor, 1 MOhm, ± 1%, 1 W, 2512 [6332 Metric], Thick Film, High Voltage", Case Code (Imperial)=2512, Case Code (Metric)=6432, Max Operating Temperature=155°C, Max Power Dissipation=1.0W, Min Operating Temperature=-55°C, Resistor Type="Thick Film", Temperature Coefficient=100ppm/°C, Tolerance=1%, Voltage Rating=3000V
R4 R17 R24 R54: library part CMP-RES-00002-1, "SMD Chip Resistor, 475 kOhm, ± 1%, 100 mW, 0603 [1608 Metric], Thick Film, Precision", Case Code (Imperial)=0603, Case Code (Metric)=1608, Max Operating Temperature=155°C, Max Power Dissipation=100mW, Min Operating Temperature=-55°C, Package Quantity=1, Resistor Type="Thick Film", Temperature Coefficient=100ppm/°C, Tolerance=1%, Voltage Rating=75V
R5 R8 R12 R23 R26 R27 R58: library part CMP-RES-00000-4, "Res Thick Film 0603 1M Ohm 1% 1/10W ±100ppm/°C Molded SMD Punched Carrier T/R", Case Code (Imperial)=0603, Case Code (Metric)=1608, Max Operating Temperature=155°C, Max Power Dissipation=100mW, Min Operating Temperature=-55°C, Package Quantity=1, Resistor Type="Thick Film", Temperature Coefficient=100ppm/°C, Tolerance=1%, Voltage Rating=75V
R6 R39 R47: library part CMP-RES-00064-1, "Res Thin Film 0603 4.22K Ohm 0.1% 1/10W ±25ppm/°C Molded SMD SMD Punched Carrier T/R", Case Code (Imperial)=0603, Case Code (Metric)=1608, Max Operating Temperature=155°C, Max Power Dissipation=100mW, Min Operating Temperature=-55°C, Package Quantity=5000, Ratings=AEC-Q200, Resistor Type="Thin Film", Temperature Coefficient=25ppm/°C, Tolerance=0.1%, Voltage Rating=75V
R7 R9 R50 R59: library part CMP-RES-00004-3, "Resistor Thick Film 0603 100K Ohm 1% 1/10W 100ppm/C Molded SMD Punched Carrier T/R", Case Code (Imperial)=0603, Case Code (Metric)=1608, Max Operating Temperature=155°C, Max Power Dissipation=100mW, Min Operating Temperature=-55°C, Package Quantity=5000, Resistor Type="Thick Film", Temperature Coefficient=100ppm/°C, Tolerance=1%, Voltage Rating=75V
R11: library part CMP-RES-00063-1, "Res Thin Film 0603 17.4K Ohm 0.1% 0.1W(1/10W) ±25ppm/C Pad SMD Automotive T/R", Case Code (Imperial)=0603, Case Code (Metric)=1608, Max Operating Temperature=155°C, Max Power Dissipation=100mW, Min Operating Temperature=-55°C, Package Quantity=5000, Ratings=AEC-Q200, Resistor Type="Thin Film", Temperature Coefficient=25ppm/°C, Tolerance=0.1%, Voltage Rating=75V
R13 R19 R25 R32 R44 R62: library part CMP-RES-00062-1, "Res Thin Film 0603 27.4K Ohm 0.1% 0.1W(1/10W) ±25ppm/C Pad SMD Automotive T/R", Case Code (Imperial)=0603, Case Code (Metric)=1608, Max Operating Temperature=155°C, Max Power Dissipation=100mW, Min Operating Temperature=-55°C, Package Quantity=5000, Ratings=AEC-Q200, Resistor Type="Thin Film", Temperature Coefficient=25ppm/°C, Tolerance=0.1%, Voltage Rating=75V
R15 R29: library part CMP-RES-00060-1, "Res Thick Film 0603 140K Ohm 1% 1/10W ±100ppm/°C Molded SMD SMD Paper T/R", Case Code (Imperial)=0603, Case Code (Metric)=1608, Max Operating Temperature=155°C, Max Power Dissipation=100mW, Min Operating Temperature=-55°C, Resistor Type="Thick Film", Temperature Coefficient=100ppm/°C, Tolerance=1%, Voltage Rating=75V
R16 R18: library part CMP-RES-00016-2, "Res Thick Film 0603 10K Ohm 1% 1/10W ±100ppm/°C Molded SMD SMD Paper T/R", Case Code (Imperial)=0603, Case Code (Metric)=1608, Max Operating Temperature=155°C, Max Power Dissipation=100mW, Min Operating Temperature=-55°C, Ratings=AEC-Q200, Resistor Type="Thick Film", Temperature Coefficient=100ppm/°C, Tolerance=1%, Voltage Rating=75V
R20: library part CMP-RES-00061-1, "Res Thick Film 0603 2.74K Ohm 1% 1/10W ±100ppm/°C Molded SMD SMD Paper T/R", Case Code (Imperial)=0603, Case Code (Metric)=1608, Max Operating Temperature=155°C, Max Power Dissipation=100mW, Min Operating Temperature=-55°C, Resistor Type="Thick Film", Temperature Coefficient=100ppm/°C, Tolerance=1%, Voltage Rating=75V
R21: library part CMP-RES-00012-1, "SMD Chip Resistor, 221 Ohm, ± 1%, 100 mW, 0603 [1608 Metric], Thick Film, Precision", Case Code (Imperial)=0603, Case Code (Metric)=1608, Max Operating Temperature=155°C, Max Power Dissipation=100mW, Min Operating Temperature=-55°C, Package Quantity=1, Resistor Type="Thick Film", Temperature Coefficient=100ppm/°C, Tolerance=1%, Voltage Rating=75V
R28: library part CMP-RES-00008-1, "Res Thick Film 0603 33.2K Ohm 1% 1/10W +/-100ppm/ßC Molded SMD Punched Carrier T/R", Case Code (Imperial)=0603, Case Code (Metric)=1608, Max Operating Temperature=155°C, Max Power Dissipation=100mW, Min Operating Temperature=-55°C, Resistor Type="Thick Film", Temperature Coefficient=100ppm/°C, Tolerance=1%, Voltage Rating=50V
R31: library part CMP-RES-00065-1, "Res Thin Film 0603 3.4K Ohm 0.1% 0.1W(1/10W) ±25ppm/C Pad SMD Automotive T/R", Case Code (Imperial)=0603, Case Code (Metric)=1608, Max Operating Temperature=155°C, Max Power Dissipation=100mW, Min Operating Temperature=-55°C, Package Quantity=1, Ratings=AEC-Q200, Resistor Type="Thin Film", Temperature Coefficient=25ppm/°C, Tolerance=0.1%, Voltage Rating=75V
R48 R49 R52 R56: library part CMP-009-00190-2, "Res Thick Film 0603 1K Ohm 1% 1/10W ±100ppm/°C Molded SMD Punched Carrier T/R", Case Code (Imperial)=0603, Case Code (Metric)=1608, Max Operating Temperature=155°C, Max Power Dissipation=100mW, Min Operating Temperature=-55°C, Resistor Type="Thick Film", Temperature Coefficient=100ppm/°C, Tolerance=1%, Voltage Rating=75V
R64: library part CMP-RES-00066-1, "Res Thin Film 0603 6.2K Ohm 0.1% 1/10W ±25ppm/°C Molded SMD SMD Punched Carrier T/R", Case Code (Imperial)=0603, Case Code (Metric)=1608, Max Operating Temperature=155°C, Max Power Dissipation=100mW, Min Operating Temperature=-55°C, Package Quantity=1, Ratings=AEC-Q200, Resistor Type="Thin Film", Temperature Coefficient=25ppm/°C, Tolerance=0.1%, Voltage Rating=75V
R181: library part CMP-RES-00069-1, "SMD Chip Resistor, 100 Ohm, ± 1%, 500 mW, 0805 [2012 Metric], Thick Film, Anti-Surge", Case Code (Imperial)=0805, Case Code (Metric)=2012, Max Operating Temperature=155°C, Max Power Dissipation=500mW, Min Operating Temperature=-55°C, Ratings=AEC-Q200, Temperature Coefficient=100ppm/°C, Tolerance=1%, Voltage Rating=150V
